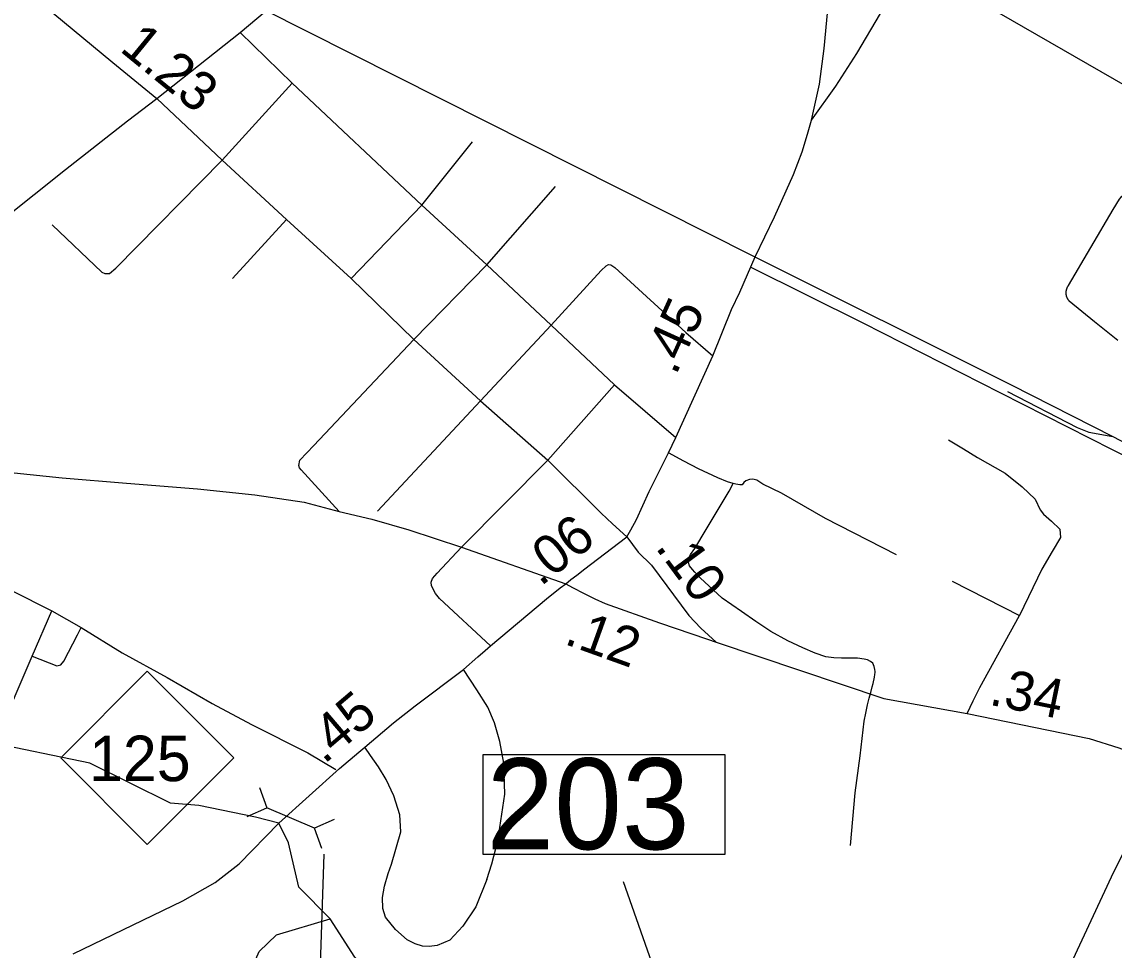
# Model space of a CAD drawing. Extents: x 2290615 to 2522933, y 819489 to 1012715.
# Drawn here: x 2396333 to 2400533, y 979017 to 982586 of the extents above; entities that cross this region are included whole.
import ezdxf

# ---------------------------------------------------------------- set-up
doc = ezdxf.new("R2010")
doc.units = 0
for name, color, linetype in [('Exist Hydrographic Creek Single Shore', 7, 'Continuous'), ('Exist Hydrographic Misc Water Feature', 7, 'Continuous'), ('Exist Railroad Mainline', 7, 'Continuous'), ('Exist Railroad Siding', 7, 'Continuous'), ('Exist Road Non-System Type 51', 7, 'Continuous'), ('Exist Road Primary NC Attributed', 7, 'Continuous'), ('Exist Road Primary NC Mileage Hundredths English Label', 7, 'Continuous'), ('Exist Road Primary NC Shield CELL', 7, 'Continuous'), ('Exist Road Primary NC Shield Number Label', 7, 'Continuous'), ('Exist Road Primary NC Structure Culvert CELL', 7, 'Continuous'), ('Exist Road Primary NC Structure Culvert Number Label', 7, 'Continuous'), ('Exist Road Primary NC UnDivided 4 Lane Attributed', 7, 'Continuous'), ('Exist Road Primary US Attributed', 7, 'Continuous'), ('Exist Road Primary US Mileage Hundredths English Label', 7, 'Continuous'), ('Exist Road Primary US UnDivided 4 Lane Attributed', 7, 'Continuous'), ('Exist Road Secondary Mileage Hundredths English Label', 7, 'Continuous'), ('Exist Road Secondary Structure Standard Bridge Number Label', 7, 'Continuous'), ('Exist Road Secondary Type 51 Attributed', 7, 'Continuous')]:
    doc.layers.add(name, color=color, linetype=linetype)

msp = doc.modelspace()

# ---------------------------------------------------------------- linework, layer by layer
at = {"layer": 'Exist Hydrographic Creek Single Shore'}
for points in [[(2397518.6, 979136.9), (2397397.3, 979259.2), (2397358.2, 979428.8), (2397320.4, 979504.4), (2397230.5, 979527.9), (2397012.7, 979572.4), (2396904.7, 979581.1), (2396594.6, 979735.8), (2395800.7, 979900), (2395674.5, 979980.2), (2395546.6, 980204.8), (2395459.7, 980444.2), (2395291.5, 980585), (2395199.6, 980607.5), (2394784.6, 980495.2), (2394592.7, 980507)], [(2400493.7, 975362.3), (2400441.6, 975468.5), (2400471.7, 975761.9), (2400460.7, 975935.4), (2400418.6, 976019.1), (2400182.6, 976183.4), (2399850.6, 976721.3), (2399706.7, 976892.6), (2399225.6, 977345.6), (2399055.7, 977617.6), (2398761.6, 977756.6), (2398702.8, 977819.9), (2398633.7, 978010.7), (2398532.6, 978101.7), (2398456.7, 978124.9), (2398372.6, 978233.1), (2398354.6, 978275), (2397823.7, 978768.5), (2397612.7, 978989.7), (2397518.6, 979136.9)]]:
    msp.add_lwpolyline(points, dxfattribs=at)
at = {"layer": 'Exist Hydrographic Misc Water Feature'}
msp.add_lwpolyline([(2393843.6, 975450), (2394034.7, 975467.7), (2394273.6, 975694.2), (2394297.6, 975770.7), (2394411.6, 975923.1), (2394988.6, 976439.3), (2395409.6, 976670), (2395499.6, 976805.1), (2395611.6, 977147.8), (2395694.6, 977223.4), (2396357.6, 977513.3), (2396762.8, 977753.1), (2396868.6, 977879), (2396948.7, 978164.7), (2397037.7, 978316.1), (2397194.6, 978460.4), (2397192.5, 978601.5), (2397166.7, 978666), (2397172.7, 978843.6), (2397245.7, 979010.7), (2397311.7, 979075.8), (2397518.6, 979136.9)], dxfattribs=at)
at = {"layer": 'Exist Railroad Mainline'}
for points in [[(2396749, 982893.3), (2399138.7, 981689.2), (2400137.1, 981190.5), (2400527.7, 980991.8)], [(2400527.7, 980991.8), (2401184.5, 980648.6)]]:
    msp.add_lwpolyline(points, dxfattribs=at)
at = {"layer": 'Exist Railroad Siding'}
msp.add_lwpolyline([(2400123.5, 981164.3), (2400391.4, 981025.8), (2400435.5, 981008.4), (2400527.7, 980991.8)], dxfattribs=at)
at = {"layer": 'Exist Road Non-System Type 51'}
for p, q in [((2397172.7, 982545.4), (2397863.8, 983128.1)), ((2397172.7, 982545.4), (2397863.8, 983128.1)), ((2396852.2, 982291.5), (2397172.7, 982545.4)), ((2396852.2, 982291.5), (2397172.7, 982545.4)), ((2397371.9, 982350.3), (2397172.7, 982545.4)), ((2397371.9, 982350.3), (2397172.7, 982545.4)), ((2397103.2, 982054.1), (2397371.9, 982350.3)), ((2397103.2, 982054.1), (2397371.9, 982350.3)), ((2397371.9, 982350.3), (2397871.3, 981881.4)), ((2397371.9, 982350.3), (2397871.3, 981881.4)), ((2397871.3, 981881.4), (2398065, 982124.9)), ((2397871.3, 981881.4), (2398065, 982124.9)), ((2398120.3, 981651.1), (2398385.2, 981953.2)), ((2398120.3, 981651.1), (2398385.2, 981953.2)), ((2397599.1, 981599.2), (2397871.3, 981881.4)), ((2397599.1, 981599.2), (2397871.3, 981881.4)), ((2397871.3, 981881.4), (2398120.3, 981651.1)), ((2397871.3, 981881.4), (2398120.3, 981651.1)), ((2397350.8, 981826.6), (2397142.1, 981598.7)), ((2397350.8, 981826.6), (2397142.1, 981598.7)), ((2397839.7, 981364.7), (2398120.3, 981651.1)), ((2397839.7, 981364.7), (2398120.3, 981651.1)), ((2398120.3, 981651.1), (2398368.6, 981419.5)), ((2398120.3, 981651.1), (2398368.6, 981419.5)), ((2398096.4, 981128.9), (2398368.6, 981419.5)), ((2398096.4, 981128.9), (2398368.6, 981419.5)), ((2398368.6, 981419.5), (2398611.2, 981190.7)), ((2398368.6, 981419.5), (2398611.2, 981190.7)), ((2398355.4, 980900.4), (2398611.2, 981190.7)), ((2398355.4, 980900.4), (2398611.2, 981190.7)), ((2398611.2, 981190.7), (2398847.6, 980987.1)), ((2398611.2, 981190.7), (2398847.6, 980987.1)), ((2397700, 980704.2), (2398096.4, 981128.9)), ((2397700, 980704.2), (2398096.4, 981128.9)), ((2399910.7, 980435.3), (2400168.6, 980302.9)), ((2399910.7, 980435.3), (2400168.6, 980302.9)), ((2396293.1, 980399.8), (2396448, 980320.9)), ((2396293.1, 980399.8), (2396448, 980320.9)), ((2396372.1, 980146.5), (2396448, 980320.9)), ((2396372.1, 980146.5), (2396448, 980320.9)), ((2396448, 980320.9), (2396561.2, 980256.8)), ((2396448, 980320.9), (2396561.2, 980256.8)), ((2396238.1, 979834.4), (2396372.1, 980146.5)), ((2396238.1, 979834.4), (2396372.1, 980146.5)), ((2399597.2, 980007.2), (2399603, 980029)), ((2399591.2, 979985.5), (2399597.2, 980007.2))]:
    msp.add_line(p, q, dxfattribs=at)
for points in [[(2399369.7, 982208.2), (2399463.3, 982338.7), (2399543.3, 982464.6), (2399634.7, 982617.9), (2399744.8, 982811.8)], [(2399369.7, 982208.2), (2399463.3, 982338.7), (2399543.3, 982464.6), (2399634.7, 982617.9), (2399744.8, 982811.8)], [(2395350.6, 981097), (2395489.6, 981208), (2395801.2, 981454.7), (2396144.5, 981734.8), (2396500.1, 982018.4), (2396739.5, 982205.2), (2396852.2, 982291.5)], [(2396449.5, 981805.5), (2396639.9, 981624), (2396652, 981618.1), (2396670, 981618.5), (2396693.7, 981638.9), (2397103.2, 982054.1)], [(2396449.5, 981805.5), (2396639.9, 981624), (2396652, 981618.1), (2396670, 981618.5), (2396693.7, 981638.9), (2397103.2, 982054.1)], [(2400833.3, 981788.6), (2400609, 981914), (2400598.3, 981919.1), (2400590.7, 981920.6), (2400583.2, 981921.6), (2400574.1, 981919.1), (2400564.8, 981915.3), (2400558.8, 981911.8), (2400551.8, 981904.7), (2400528.6, 981864.5), (2400356.8, 981571.9)], [(2398368.6, 981419.5), (2398504.7, 981569.3), (2398560.8, 981629.7), (2398579.4, 981647.9), (2398589.2, 981652.9), (2398597.3, 981652.2), (2398612.7, 981640.9), (2398886.3, 981391), (2398990.1, 981301.2)], [(2399135.7, 981643.1), (2399566.7, 981429.1), (2400096.6, 981159.1), (2400525.9, 980941.7), (2400758, 980823.9), (2400932.9, 980730), (2401080.3, 980657.3), (2401268, 980563.4), (2401744.3, 980321.6), (2402255.8, 980060.9), (2402471.7, 979948.2)], [(2399135.7, 981643.1), (2399566.7, 981429.1), (2400096.6, 981159.1), (2400525.9, 980941.7), (2400758, 980823.9), (2400932.9, 980730), (2401080.3, 980657.3), (2401268, 980563.4), (2401744.3, 980321.6), (2402255.8, 980060.9), (2402471.7, 979948.2)], [(2400356.8, 981571.9), (2400356.4, 981571.3), (2400355.9, 981570.7), (2400355.4, 981570), (2400355, 981569.4), (2400354.6, 981568.7), (2400354.1, 981568.1), (2400353.7, 981567.4), (2400353.3, 981566.7), (2400352.9, 981566.1), (2400352.6, 981565.4), (2400352.2, 981564.7), (2400351.9, 981564), (2400351.5, 981563.3), (2400351.2, 981562.6), (2400350.9, 981561.9), (2400350.6, 981561.1), (2400350.3, 981560.4), (2400350, 981559.7), (2400349.7, 981558.9), (2400349.5, 981558.2), (2400349.3, 981557.4), (2400349, 981556.7), (2400348.8, 981555.9), (2400348.6, 981555.2), (2400348.4, 981554.4), (2400348.3, 981553.7), (2400348.1, 981552.9), (2400348, 981552.1), (2400347.8, 981551.4), (2400347.7, 981550.6), (2400347.6, 981549.8), (2400347.5, 981549), (2400347.4, 981548.2), (2400347.4, 981547.5), (2400347.3, 981546.7), (2400347.3, 981545.9), (2400347.2, 981545.1), (2400347.2, 981544.3), (2400347.2, 981543.6), (2400347.2, 981542.8), (2400347.3, 981542), (2400347.3, 981541.2), (2400347.4, 981540.4), (2400347.4, 981539.6), (2400347.5, 981538.9), (2400347.6, 981538.1), (2400347.7, 981537.3), (2400347.9, 981536.5), (2400348, 981535.8), (2400348.1, 981535), (2400348.3, 981534.2), (2400348.5, 981533.5), (2400348.7, 981532.7), (2400348.9, 981532), (2400349.1, 981531.2), (2400349.3, 981530.5), (2400349.6, 981529.7), (2400349.8, 981529), (2400350.1, 981528.2), (2400350.4, 981527.5), (2400350.7, 981526.8), (2400351, 981526.1), (2400351.3, 981525.3), (2400351.6, 981524.6), (2400352, 981523.9), (2400352.3, 981523.2), (2400352.7, 981522.5), (2400353.1, 981521.9), (2400353.5, 981521.2), (2400353.9, 981520.5), (2400354.3, 981519.8), (2400354.7, 981519.2), (2400355.1, 981518.5), (2400355.6, 981517.9), (2400356, 981517.3), (2400356.5, 981516.6), (2400357, 981516), (2400357.5, 981515.4), (2400358, 981514.8), (2400358.5, 981514.2), (2400359, 981513.6), (2400359.6, 981513)], [(2400359.6, 981513), (2400457.4, 981434.2), (2400547.1, 981361.4)], [(2397552.8, 980703.8), (2397406.7, 980863.3), (2397400.1, 980870.8), (2397397.3, 980880.6), (2397401.8, 980901), (2397455.8, 980957.1), (2397839.7, 981364.7)], [(2397552.8, 980703.8), (2397406.7, 980863.3), (2397400.1, 980870.8), (2397397.3, 980880.6), (2397401.8, 980901), (2397455.8, 980957.1), (2397839.7, 981364.7)], [(2399895.5, 980978.6), (2399954, 980943.9), (2400008.2, 980911.3), (2400114.5, 980850.6), (2400179.5, 980798.6), (2400229.3, 980750.8), (2400248.8, 980709.6), (2400261.8, 980693.4), (2400292.2, 980666.3), (2400324.7, 980635.9), (2400326.9, 980603.4), (2400294.4, 980549.1), (2400255.3, 980481.9), (2400168.6, 980302.9)], [(2399895.5, 980978.6), (2399954, 980943.9), (2400008.2, 980911.3), (2400114.5, 980850.6), (2400179.5, 980798.6), (2400229.3, 980750.8), (2400248.8, 980709.6), (2400261.8, 980693.4), (2400292.2, 980666.3), (2400324.7, 980635.9), (2400326.9, 980603.4), (2400294.4, 980549.1), (2400255.3, 980481.9), (2400168.6, 980302.9)], [(2399068.6, 980810.9), (2399045.8, 980817), (2399009, 980832.2), (2398935.3, 980866.9), (2398878.9, 980897.3), (2398819.3, 980928.2)], [(2398134.8, 980186.7), (2397938.9, 980368.5), (2397922.7, 980388.2), (2397908.3, 980418), (2397907.2, 980431.9), (2397911.9, 980446), (2397929.7, 980466.3), (2398023.4, 980566), (2398355.4, 980900.4)], [(2399696.1, 980537.2), (2399423, 980676), (2399253.9, 980773.6), (2399182.4, 980808.3), (2399158.5, 980823.5), (2399143.3, 980827.8), (2399130.3, 980825.7), (2399117.3, 980821.3), (2399108.7, 980814.8), (2399102.2, 980806.2), (2399093.5, 980806.2), (2399078.3, 980808.3), (2399068.6, 980810.9)], [(2399613.7, 980087.8), (2399612.8, 980096.2), (2399610.3, 980107.4), (2399605.3, 980119.9), (2399596.6, 980126.2), (2399584.1, 980132.4), (2399571.6, 980134.9), (2399546.6, 980138.7), (2399519.1, 980138.7), (2399484.2, 980138.7), (2399455.4, 980139.9), (2399424.2, 980144.9), (2399383, 980158.7), (2399335.5, 980178.7), (2399278, 980206.2), (2399213.1, 980242.4), (2399155.6, 980279.9), (2399100.7, 980318.7), (2399025.7, 980369.9), (2398974.5, 980417.4), (2398942, 980447.4), (2398920.8, 980469.9), (2398912, 980479.9), (2398899.6, 980493.7), (2398895.8, 980507.4), (2398895.8, 980521.2), (2398904.5, 980537.4), (2398920.8, 980561.2), (2398964.5, 980633.7), (2399053.2, 980781.2), (2399068.6, 980810.9)], [(2400005.4, 980003.4), (2400017, 980026), (2400168.6, 980302.9)], [(2396372.1, 980146.5), (2396467.4, 980109.3), (2396482.3, 980113.8), (2396494.2, 980127.2), (2396546.4, 980228.9), (2396561.2, 980256.8)], [(2396372.1, 980146.5), (2396467.4, 980109.3), (2396482.3, 980113.8), (2396494.2, 980127.2), (2396546.4, 980228.9), (2396561.2, 980256.8)], [(2396561.2, 980256.8), (2396719, 980159.9), (2396891.7, 980064.6), (2397064.4, 979964.8), (2397216.3, 979884.3), (2397432.2, 979775.5), (2397540.6, 979711.7)], [(2396561.2, 980256.8), (2396719, 980159.9), (2396891.7, 980064.6), (2397064.4, 979964.8), (2397216.3, 979884.3), (2397432.2, 979775.5), (2397540.6, 979711.7)], [(2398120.6, 979288), (2398140, 979348.2), (2398162.8, 979436.4), (2398190.1, 979616.1), (2398185.7, 979735.3), (2398170.8, 979818.8), (2398149.9, 979890.3), (2398124.6, 979951.4), (2398082.9, 980016.9), (2398030.8, 980095.9)], [(2398120.6, 979288), (2398140, 979348.2), (2398162.8, 979436.4), (2398190.1, 979616.1), (2398185.7, 979735.3), (2398170.8, 979818.8), (2398149.9, 979890.3), (2398124.6, 979951.4), (2398082.9, 980016.9), (2398030.8, 980095.9)], [(2399603, 980029), (2399606.6, 980042.4), (2399611.6, 980066.2), (2399612.8, 980076.2), (2399614.1, 980083.7), (2399613.7, 980087.8)], [(2399577.6, 979927.5), (2399584.1, 979959.9), (2399591.2, 979985.5)], [(2399967.8, 979926.3), (2399990.6, 979974.8), (2400005.4, 980003.4)], [(2399519.1, 979418.7), (2399536.6, 979621.2), (2399556.6, 979763.7), (2399571.6, 979897.4), (2399577.6, 979927.5)], [(2398120.6, 979288), (2398078.5, 979183.3), (2398027.8, 979108.8), (2397978.7, 979055.2), (2397929.6, 979034.3), (2397899, 979031), (2397873.7, 979032.4), (2397844.7, 979041.4), (2397814.2, 979056.3), (2397769.5, 979095.8), (2397731.5, 979143.4), (2397721.1, 979176.2), (2397719.6, 979219.1), (2397727.1, 979262.3), (2397741.9, 979311.4), (2397753.9, 979347.2), (2397790.3, 979471.5), (2397786.6, 979537.2), (2397762.8, 979609.8), (2397733, 979672.7), (2397704.7, 979721.9), (2397673.5, 979765.1), (2397651.1, 979796.4)]]:
    msp.add_lwpolyline(points, dxfattribs=at)
at = {"layer": 'Exist Road Primary NC Attributed'}
for points in [[(2399152.9, 981682.1), (2399226.8, 981836.3), (2399300.5, 981999.2), (2399333.4, 982085.8), (2399354.4, 982153.9), (2399369.7, 982208.2), (2399399.9, 982346.5), (2399417.5, 982482.9), (2399438.1, 982702.5), (2399454.8, 982868)], [(2398659.2, 980605.8), (2398675.1, 980633.2), (2398695.7, 980672.2), (2398745.6, 980780.7), (2398819.3, 980928.2), (2398847.6, 980987.1), (2398990.1, 981301.2), (2399061.4, 981479.4), (2399093.4, 981547), (2399152.9, 981682.1)]]:
    msp.add_lwpolyline(points, dxfattribs=at)
at = {"layer": 'Exist Road Primary NC Shield CELL'}
msp.add_lwpolyline([(2396482.1, 979756), (2396815.1, 980089), (2397148.1, 979756), (2396815.1, 979423)], close=True, dxfattribs=at)
at = {"layer": 'Exist Road Primary NC Structure Culvert CELL'}
for p, q in [((2397246.1, 979641.7), (2397275, 979563.6)), ((2397198.6, 979530.5), (2397275, 979563.6)), ((2397457.4, 979485.6), (2397275, 979563.6)), ((2397533.8, 979518.6), (2397457.4, 979485.6)), ((2397486.3, 979407.4), (2397457.4, 979485.6))]:
    msp.add_line(p, q, dxfattribs=at)
at = {"layer": 'Exist Road Primary NC Structure Culvert Number Label'}
msp.add_lwpolyline([(2397493.5, 979385.8), (2397466.9, 978573.3), (2396547.8, 977441.2)], dxfattribs=at)
at = {"layer": 'Exist Road Primary NC UnDivided 4 Lane Attributed'}
for points in [[(2398423.9, 980425.2), (2398444.2, 980441.1), (2398466.4, 980458.6), (2398497.8, 980483.3), (2398518.8, 980499.8), (2398659.2, 980605.8)], [(2396530.6, 979002), (2396951.5, 979205.7), (2397076.6, 979276.2), (2397167.9, 979347.9), (2397320.4, 979504.4), (2397554, 979714.7), (2397628.8, 979778.2), (2397651.1, 979796.4), (2397761.3, 979890.3), (2397844.7, 979955.8), (2398030.8, 980095.9), (2398086.6, 980144.7), (2398114.2, 980168.5), (2398134.8, 980186.7), (2398350.1, 980367), (2398370.1, 980383.8), (2398395.5, 980403.4), (2398403.2, 980409.3), (2398423.9, 980425.2)]]:
    msp.add_lwpolyline(points, dxfattribs=at)
at = {"layer": 'Exist Road Primary US Attributed'}
msp.add_lwpolyline([(2393877.1, 981681.9), (2394220.4, 981548), (2394806.6, 981304.9), (2394980.9, 981236.2), (2395121.7, 981179.8), (2395350.6, 981097), (2395435.1, 981061.8), (2395528.4, 981026.6), (2395612.9, 980996.6), (2395737.9, 980957.8), (2395858.4, 980931.7), (2396077.2, 980884.1), (2396303.6, 980852), (2396488.2, 980832.6), (2396735.4, 980811.8), (2397007.9, 980790.9), (2397228.2, 980767.1), (2397418.8, 980739.5), (2397552.8, 980703.8), (2397677.9, 980674), (2397820.9, 980632.3), (2398023.4, 980566), (2398423.9, 980425.2)], dxfattribs=at)
at = {"layer": 'Exist Road Primary US UnDivided 4 Lane Attributed'}
for points in [[(2398423.9, 980425.2), (2398450, 980410.9), (2398494.7, 980387.4), (2398535.8, 980367.6), (2398575.4, 980349.8), (2398784.1, 980274.5), (2398969.3, 980211.8), (2399002.7, 980200.6)], [(2399002.7, 980200.6), (2399646.9, 979983.6), (2399967.8, 979926.3), (2400437.1, 979830.8), (2400550.7, 979794.6), (2400740.1, 979723.8)]]:
    msp.add_lwpolyline(points, dxfattribs=at)
at = {"layer": 'Exist Road Secondary Structure Standard Bridge Number Label'}
msp.add_line((2399406.4, 977127.6), (2398645.8, 979279.7), dxfattribs=at)
msp.add_lwpolyline([(2398107.1, 979768.6), (2399036.1, 979768.6), (2399036.1, 979384.5), (2398107.1, 979384.5)], close=True, dxfattribs=at)
at = {"layer": 'Exist Road Secondary Type 51 Attributed'}
for points in [[(2401764.1, 981671.4), (2400969.2, 982114.9), (2399749.4, 982816.9), (2399637.2, 982852.7), (2399454.8, 982868)], [(2396377.3, 982683), (2396682.4, 982430.3), (2396852.2, 982291.5), (2397103.2, 982054.1), (2397350.8, 981826.6), (2397599.1, 981599.2), (2397839.7, 981364.7), (2398096.4, 981128.9), (2398355.4, 980900.4), (2398560.9, 980697.1), (2398604.1, 980655.3), (2398659.2, 980605.8)], [(2398659.2, 980605.8), (2398702.4, 980547.3), (2398754.5, 980496.7), (2398897.1, 980303.7), (2398943.7, 980254.2), (2399002.7, 980200.6)], [(2399791.8, 977715.2), (2400366.9, 978962.9), (2400531.6, 979318.1), (2400626.8, 979506.2), (2400740.1, 979723.8)]]:
    msp.add_lwpolyline(points, dxfattribs=at)

# ---------------------------------------------------------------- texts
at = {"layer": 'Exist Road Primary NC Mileage Hundredths English Label'}
for s, rotation, p in [('.45', 65.6039, (2398847.5, 981223.3)), ('.06', 38.1826, (2398327.1, 980412.7)), ('.45', 40.4267, (2397495, 979729.1))]:
    msp.add_text(s, height=150, rotation=rotation, dxfattribs=at).set_placement(p)
at = {"layer": 'Exist Road Primary NC Shield Number Label'}
msp.add_text('125', height=175, dxfattribs=at).set_placement((2396591.2, 979666.3))
at = {"layer": 'Exist Road Primary US Mileage Hundredths English Label'}
for s, rotation, p in [('.12', 340.1715, (2398413.9, 980195.4)), ('.34', 348.4969, (2400048.4, 979961))]:
    msp.add_text(s, height=150, rotation=rotation, dxfattribs=at).set_placement(p)
at = {"layer": 'Exist Road Secondary Mileage Hundredths English Label'}
for s, rotation, p in [('1.23', 320.7363, (2396704.8, 982476.5)), ('.10', 306.4572, (2398766, 980565.2))]:
    msp.add_text(s, height=150, rotation=rotation, dxfattribs=at).set_placement(p)
at = {"layer": 'Exist Road Secondary Structure Standard Bridge Number Label'}
msp.add_text('203', height=350, dxfattribs=at).set_placement((2398119.6, 979404.3))

doc.saveas('drawing.dxf')
